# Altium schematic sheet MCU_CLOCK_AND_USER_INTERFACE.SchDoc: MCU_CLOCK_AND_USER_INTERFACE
size A4; Date: Not used; ApprovedBy: Not used; CheckedBy: Not used; Author: Not used; CompanyName: STMicroelectronics; DrawnBy: Not used; Engineer: Not used; Organization: Not used; Address1: Not used; Address2: Not used; Address3: Not used; Address4: Not used; DocumentNumber: Not used; Revision: Not used; SheetNumber: 4; SheetTotal: 16
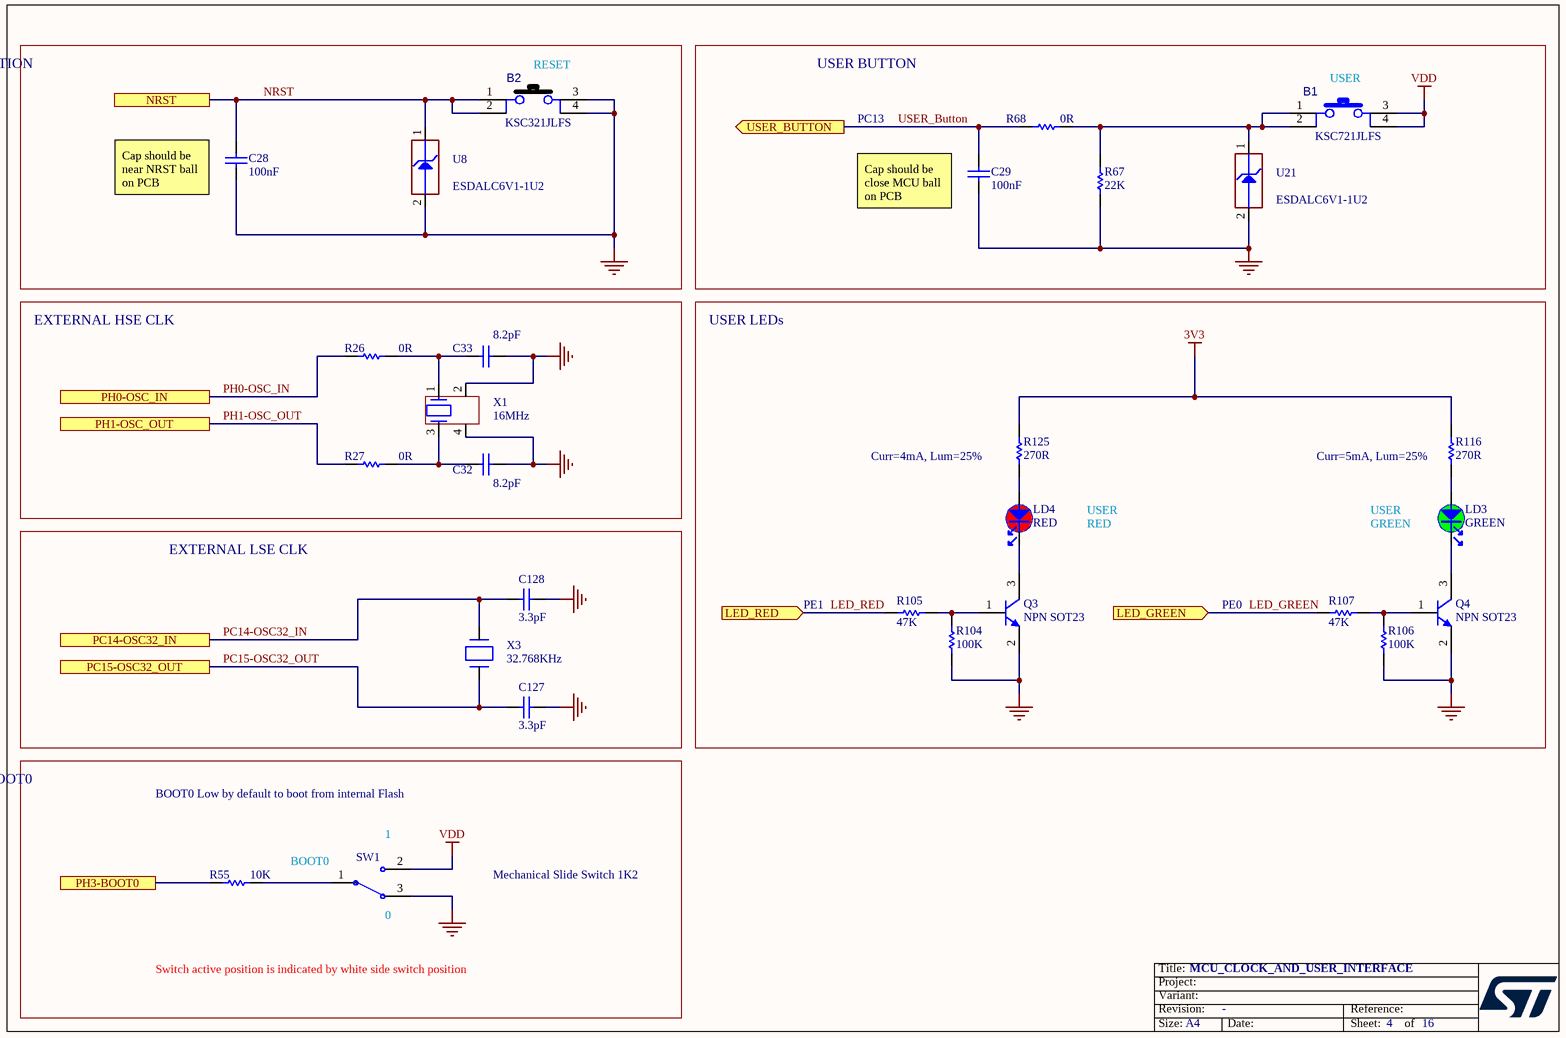
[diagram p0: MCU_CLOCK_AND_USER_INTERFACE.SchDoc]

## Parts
B1  value KSC721JLFS  [SWI_C&K_KSC721JLFS_BLUE]  (hidden comment: SW_BLUE_KSC721JLFS)
B2  value KSC321JLFS  [SWI_C&K_KSC321JLFS_BLACK]  (hidden comment: SW_BLACK_KSC321JLFS)
C28  value 100nF  [C0402]  (hidden comment: Capacitor)
C29  value 100nF  [C0402]  (hidden comment: Capacitor)
C32  value 8.2pF  [C0402]  (hidden comment: Capacitor)
C33  value 8.2pF  [C0402]  (hidden comment: Capacitor)
C127  value 3.3pF  [C0402]  (hidden comment: Capacitor)
C128  value 3.3pF  [C0402]  (hidden comment: Capacitor)
LD3  value GREEN  [LED_0603_OSRAM_LG-Q396-PS-35_GREEN_1A2K_H0P4]  (hidden comment: LED_green)
LD4  value RED  [LED_0603_OSRAM_LS-Q976-NR-1_RED_1A2K_H0P8]  (hidden comment: LED_red)
Q3  value NPN SOT23  [NPN_SOT23]  (hidden comment: 9013-SOT23)
Q4  value NPN SOT23  [NPN_SOT23]  (hidden comment: 9013-SOT23)
R26  value 0R  [R0402]  (hidden comment: Resistor)
R27  value 0R  [R0402]  (hidden comment: Resistor)
R55  value 10K  [R0603]  (hidden comment: Resistor)
R67  value 22K  [R0603]  (hidden comment: Resistor)
R68  value 0R  [R0603]  (hidden comment: Resistor)
R104  value 100K  [R0603]  (hidden comment: Resistor)
R105  value 47K  [R0603]  (hidden comment: Resistor)
R106  value 100K  [R0603]  (hidden comment: Resistor)
R107  value 47K  [R0603]  (hidden comment: Resistor)
R116  value 270R  [R0402]  (hidden comment: Resistor)
R125  value 270R  [R0402]  (hidden comment: Resistor)
SW1  value Mechanical Slide Switch 1K2  [SWI_EAO_09-03290-01_EXTENDED_STRAIGHT_BLACK]  (hidden comment: SW_MECA_1K2)
U8  value ESDALC6V1-1U2  [ESD_ST0201]  (hidden comment: ESD-TRANSIL)
U21  value ESDALC6V1-1U2  [ESD_ST0201]  (hidden comment: ESD-TRANSIL)
X1  value 16MHz  [CRY_NX2016SA_4P]  (hidden comment: XTAL_4_PINS)
X3  value 32.768KHz  [CRY_NX2012SA_2P]  (hidden comment: XTAL_2_PINS)

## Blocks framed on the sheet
RESET FUNCTION: B2 C28 U8
USER BUTTON: B1 C29 R67 R68 U21
EXTERNAL HSE CLK: C32 C33 R26 R27 X1
USER LEDs: LD3 LD4 Q3 Q4 R104-R107 R116 R125
EXTERNAL LSE CLK: C127 C128 X3
PH3_BOOT0: R55 SW1

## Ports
LED_GREEN (in), LED_RED (in), NRST, PC14-OSC32_IN, PC15-OSC32_OUT, PH0-OSC_IN, PH1-OSC_OUT, PH3-BOOT0, USER_BUTTON (out)

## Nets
3V3: R116.2 R125.2
GND: B2.3 B2.4 C28.1 C29.1 C32.2 C33.2 C127.2 C128.2 Q3.2(E) Q4.2(E) R67.1 R104.1 R106.1 SW1.3 U8.2(GND) U21.2(GND) X1.2 X1.4
VDD: B1.3 B1.4 SW1.2
LED_GREEN: R107.1 ; port LED_GREEN
LED_RED: R105.1 ; port LED_RED
NRST: B2.1 B2.2 C28.2 U8.1(IO1) ; port NRST
PC14-OSC32_IN: C128.1 X3.2(X2) ; port PC14-OSC32_IN
PC15-OSC32_OUT: C127.1 X3.1(X1) ; port PC15-OSC32_OUT
PH0-OSC_IN: R26.1 ; port PH0-OSC_IN
PH1-OSC_OUT: R27.1 ; port PH1-OSC_OUT
PH3-BOOT0: R55.1 ; port PH3-BOOT0
USER_Button: C29.2 R68.1 ; port USER_BUTTON
NetB1_1: B1.1 B1.2 R67.2 R68.2 U21.1(IO1)
NetC32_1: C32.1 R27.2 X1.3
NetC33_1: C33.1 R26.2 X1.1
NetLD3_1: LD3.1 R116.1
NetLD3_2: LD3.2 Q4.3(C)
NetLD4_1: LD4.1 R125.1
NetLD4_2: LD4.2 Q3.3(C)
NetQ3_1: Q3.1(B) R104.2 R105.2
NetQ4_1: Q4.1(B) R106.2 R107.2
NetR55_2: R55.2 SW1.1

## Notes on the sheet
- (near B2) RESET
- (near B1) USER
- PC13
- (near C28) Cap should be near NRST ball on PCB
- (near C29) Cap should be close MCU ball on PCB
- Curr=4mA, Lum=25%
- USER
- Curr=5mA, Lum=25%
- RED
- GREEN
- PE1
- PE0
- BOOT0 Low by default to boot from internal Flash
- (near SW1) 1
- BOOT0
- (near SW1) 0
- Switch active position is indicated by white side switch position

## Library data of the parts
B1 = MCD-01800: Switch HW BLUE High4.3mm 2.25 Newtons, BEND type; Part_Type: Misc; Manufacturer: C&K; Part_Preference: Recommended; Component_Country_Of_Origin: France
B2 = MCD-01799: Switch HW BLACK High3.5mm 2Newtons, BEND type; Part_Type: Misc; Manufacturer: C&K; Part_Preference: Recommended; Component_Country_Of_Origin: France
C28 C29 = MCD-00006: Capacitor, MLCC, 100nF, 16V, X7R, +/-10%, 0402, T=0.5mm; Manufacturer_Part_Number: CC0402KRX7R7BB104; Manufacturer: YAGEO; Part_Preference: Recommended; Order_Code_RS: 616-9701; Component_Country_Of_Origin: China
C32 C33 = MCD-01932: Capacitor, MLCC, 8.2pF, 50V, NPO, +/-0.25pF, 0402, T=0.5mm; Part_Preference: Recommended; Manufacturer: YAGEO; Manufacturer_Part_Number: CC0402CRNPO9BN8R2; Component_Country_Of_Origin: China
C127 C128 = MCD-01775: Capacitor, MLCC, 3.3pF, 50V, NPO, +/-0.1pF, 0402, T=0.5mm; Part_Preference: Recommended; Manufacturer: YAGEO; Manufacturer_Part_Number: CC0402BRNPO9BN3R3; Component_Country_Of_Origin: China
LD3 = MCD-00588: LED Green, 0603 SMD, Forward Voltage Typ=2V, Max=2.5V; Part_Type: Display; Manufacturer_Part_Number: LG Q396-PS-35; Manufacturer: OSRAM OPTO SEMICONDUCTORS; Part_Preference: Recommended; Alternate_Internal_Part_Number: MCD-02400; Component_Country_Of_Origin: Unknown; ShowFields: YES; ID: 3155
LD4 = MCD-00586: LED Red, 0603 SMD, Forward Voltage Typ=2V, Max=2.5V; Manufacturer_Part_Number: LS Q976-NR-1; Manufacturer: OSRAM OPTO SEMICONDUCTORS; Part_Type: Display; Part_Preference: Recommended; Component_Country_Of_Origin: Unknown; ShowFields: YES; ID: 3158
Q3 Q4 = MCD-00073: NPN Bipolar Transistor; Part_Type: IC; Manufacturer_Part_Number: BSR14; Manufacturer: ON SEMICONDUCTOR; Part_Preference: Recommended; Component_Country_Of_Origin: Unknown
R26 R27 = MCD-00052: Resistor, 0R, 0402, +/-5%, 1/16W; Manufacturer_Part_Number: RC0402JR-070RL; Manufacturer: YAGEO; Part_Preference: Recommended; Order_Code_RS: 618-5804; Component_Country_Of_Origin: China
R55 = MCD-00220: Resistor, 10K, 0603, +/-1%, 1/10W; Manufacturer_Part_Number: RC0603FR-0710KL; Manufacturer: YAGEO; Part_Preference: Recommended; Component_Country_Of_Origin: China
R67 = MCD-00430: Resistor, 22K, 0603, +/-1%, 1/10W; Manufacturer_Part_Number: RC0603FR-0722KL; Manufacturer: YAGEO; Part_Preference: Recommended; Component_Country_Of_Origin: China; ShowFields: YES; ID: 2847
R68 = MCD-00056: Resistor, 0R, 0603, +/-5%, 1/10W; Manufacturer_Part_Number: RC0603JR-070RL; Manufacturer: YAGEO; Part_Preference: Recommended; Component_Country_Of_Origin: China; ShowFields: YES; ID: 2536
R104 R106 = MCD-00223: Resistor, 100K, 0603, +/- 1%, 1/10W; Manufacturer_Part_Number: RC0603FR-07100KL; Manufacturer: YAGEO; Part_Preference: Recommended; Component_Country_Of_Origin: China
R105 R107 = MCD-00222: Resistor, 47K, 0603, 1%, 1/10W; Manufacturer_Part_Number: RC0603FR-0747KL; Manufacturer: YAGEO; Part_Preference: Recommended; Component_Country_Of_Origin: China
R116 = MCD-00441: Resistor, 270R, 0402, +/-1%, 1/16W; Manufacturer: YAGEO; Manufacturer_Part_Number: RC0402FR-07270RL; Part_Preference: Recommended; Component_Country_Of_Origin: China; ShowFields: YES; ID: 2838
R125 = MCD-00441: Resistor, 270R, 0402, +/-1%, 1/16W; Manufacturer_Part_Number: RC0402FR-07270RL; Manufacturer: YAGEO; Part_Preference: Recommended; Component_Country_Of_Origin: China; ShowFields: YES; ID: 2838
SW1 = MCD-00566: Mechanical Slide Switches 1K2 BLK ACT GOLD STRT MNT; Part_Preference: Recommended; Part_Type: Misc; Manufacturer: EAO; Manufacturer_Part_Number: 09.03290.01; Component_Country_Of_Origin: Switzerland
U8 U21 = MCD-00170: ESD protection 6V1; Part_Type: Diode; Manufacturer: STMICROELECTRONICS; BMS_Part_Number: 9151132; Part_Preference: Recommended; Manufacturer_HQ_COO: EU; Component_Country_Of_Origin: China
X1 = MCD-01476: Crystal, 16 MHz, 8pF, +/-20ppm, 200R, 2x1.6mm; Part_Type: Crystal_Osc; Manufacturer_Part_Number: NX2016SA-16MHZ-EXS00A-CS07826; Manufacturer: NDK; BMS_Part_Number: 9157046; Part_Preference: Recommended; Component_Country_Of_Origin: Unknown
X3 = MCD-01479: Crystal, 32.768kHz, 6pF, +/-20ppm, 80K, 2.05x1.2mm; Part_Type: Crystal_Osc; Manufacturer_Part_Number: NX2012SA-32.768KHZ-EXS00A-MU00527; Manufacturer: NDK; BMS_Part_Number: 9157049; Part_Preference: Recommended; Component_Country_Of_Origin: Unknown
